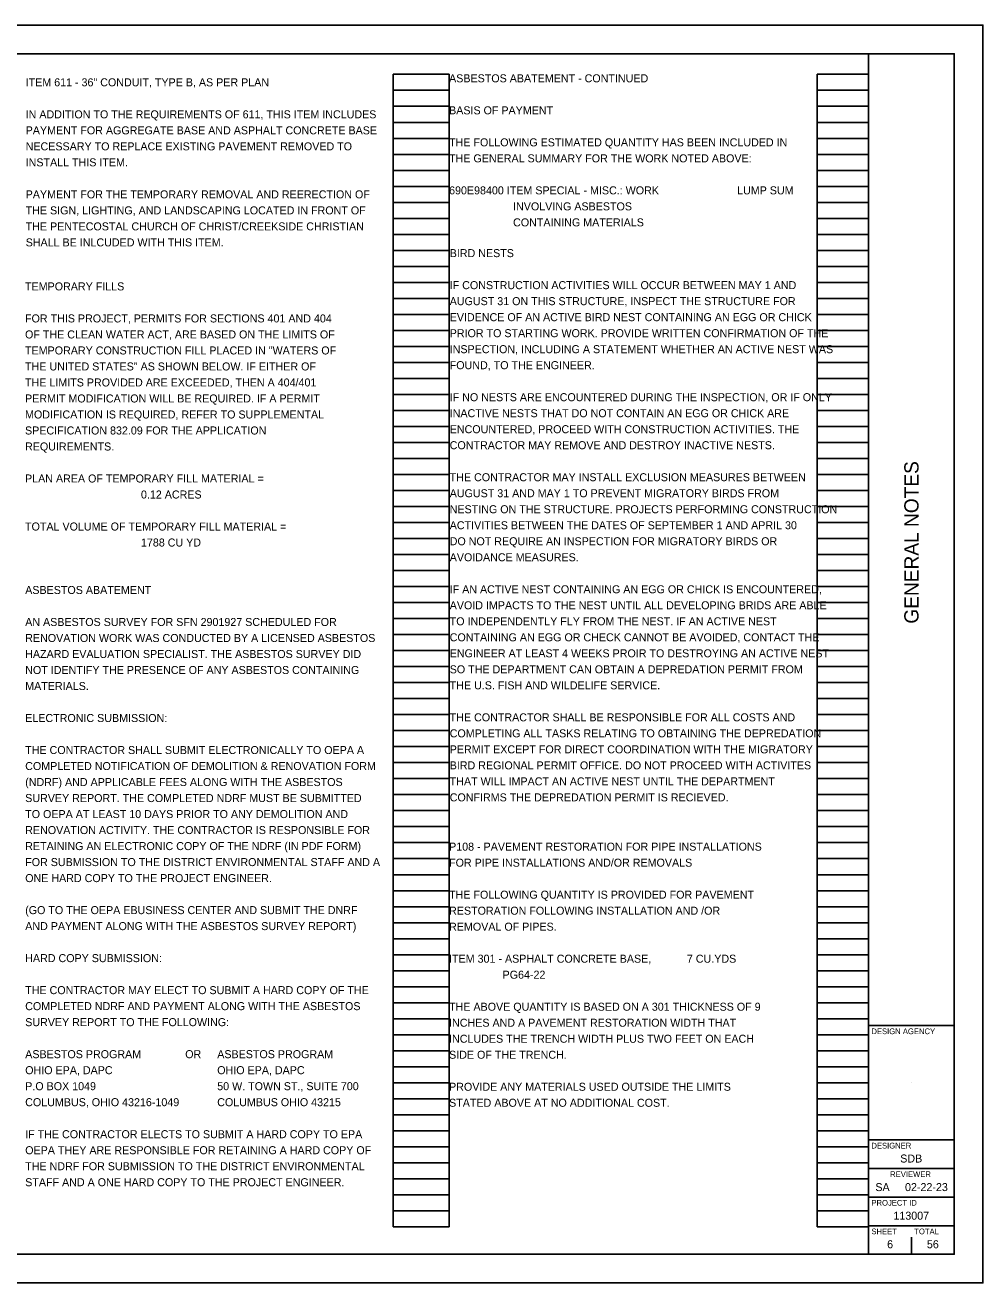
# Model space of a CAD drawing. Extents: x 0 to 34, y 0 to 22.
# Drawn here: x 17.24 to 34, y 0 to 22 of the extents above; entities that cross this region are included whole.
import ezdxf

# ---------------------------------------------------------------- set-up
doc = ezdxf.new("R2010")
doc.units = 0
for name, color, linetype in [('SH_Border', 7, 'Continuous'), ('SH_Cut_Line', 7, 'Continuous'), ('SH_Data', 7, 'Continuous'), ('SH_Text', 7, 'Continuous')]:
    doc.layers.add(name, color=color, linetype=linetype)

msp = doc.modelspace()

# ---------------------------------------------------------------- linework, layer by layer
at = {"layer": 'SH_Border'}
for p, q in [((32, 0.5), (32, 21.5)), ((32, 4.5), (33.5, 4.5)), ((32, 2.5), (33.5, 2.5)), ((32, 2), (33.5, 2)), ((32, 1.5), (33.5, 1.5)), ((32, 1), (33.5, 1))]:
    msp.add_line(p, q, dxfattribs=at)
msp.add_lwpolyline([(1.5, 21.5), (33.5, 21.5), (33.5, 0.5), (1.5, 0.5)], close=True, dxfattribs=at)
at = {"layer": 'SH_Cut_Line'}
msp.add_lwpolyline([(0, 0), (34, 0), (34, 22), (0, 22)], close=True, dxfattribs=at)
at = {"layer": 'SH_Data'}
for p, q in [((23.68, 0.98), (23.68, 21.14)), ((23.68, 21.14), (24.66, 21.14)), ((24.66, 0.98), (24.66, 21.14)), ((31.1, 0.98), (31.1, 21.14)), ((31.1, 21.14), (32, 21.14)), ((32, 0.98), (32, 21.14)), ((23.68, 20.86), (24.66, 20.86)), ((31.1, 20.86), (32, 20.86)), ((23.68, 20.58), (24.66, 20.58)), ((31.1, 20.58), (32, 20.58)), ((23.68, 20.3), (24.66, 20.3)), ((31.1, 20.3), (32, 20.3)), ((23.68, 20.02), (24.66, 20.02)), ((31.1, 20.02), (32, 20.02)), ((23.68, 19.74), (24.66, 19.74)), ((31.1, 19.74), (32, 19.74)), ((23.68, 19.46), (24.66, 19.46)), ((31.1, 19.46), (32, 19.46)), ((23.68, 19.18), (24.66, 19.18)), ((31.1, 19.18), (32, 19.18)), ((23.68, 18.9), (24.66, 18.9)), ((31.1, 18.9), (32, 18.9)), ((23.68, 18.62), (24.66, 18.62)), ((31.1, 18.62), (32, 18.62)), ((23.68, 18.34), (24.66, 18.34)), ((31.1, 18.34), (32, 18.34)), ((23.68, 18.06), (24.66, 18.06)), ((31.1, 18.06), (32, 18.06)), ((23.68, 17.78), (24.66, 17.78)), ((31.1, 17.78), (32, 17.78)), ((23.68, 17.5), (24.66, 17.5)), ((31.1, 17.5), (32, 17.5)), ((23.68, 17.22), (24.66, 17.22)), ((31.1, 17.22), (32, 17.22)), ((23.68, 16.94), (24.66, 16.94)), ((31.1, 16.94), (32, 16.94)), ((23.68, 16.66), (24.66, 16.66)), ((31.1, 16.66), (32, 16.66)), ((23.68, 16.38), (24.66, 16.38)), ((31.1, 16.38), (32, 16.38)), ((23.68, 16.1), (24.66, 16.1)), ((31.1, 16.1), (32, 16.1)), ((23.68, 15.82), (24.66, 15.82)), ((31.1, 15.82), (32, 15.82)), ((23.68, 15.54), (24.66, 15.54)), ((31.1, 15.54), (32, 15.54)), ((23.68, 15.26), (24.66, 15.26)), ((31.1, 15.26), (32, 15.26)), ((23.68, 14.98), (24.66, 14.98)), ((31.1, 14.98), (32, 14.98)), ((23.68, 14.7), (24.66, 14.7)), ((31.1, 14.7), (32, 14.7)), ((23.68, 14.42), (24.66, 14.42)), ((31.1, 14.42), (32, 14.42)), ((23.68, 14.14), (24.66, 14.14)), ((31.1, 14.14), (32, 14.14)), ((23.68, 13.86), (24.66, 13.86)), ((31.1, 13.86), (32, 13.86)), ((23.68, 13.58), (24.66, 13.58)), ((31.1, 13.58), (32, 13.58)), ((23.68, 13.3), (24.66, 13.3)), ((31.1, 13.3), (32, 13.3)), ((23.68, 13.02), (24.66, 13.02)), ((31.1, 13.02), (32, 13.02)), ((23.68, 12.74), (24.66, 12.74)), ((31.1, 12.74), (32, 12.74)), ((23.68, 12.46), (24.66, 12.46)), ((31.1, 12.46), (32, 12.46)), ((23.68, 12.18), (24.66, 12.18)), ((31.1, 12.18), (32, 12.18)), ((23.68, 11.9), (24.66, 11.9)), ((31.1, 11.9), (32, 11.9)), ((23.68, 11.62), (24.66, 11.62)), ((31.1, 11.62), (32, 11.62)), ((23.68, 11.34), (24.66, 11.34)), ((31.1, 11.34), (32, 11.34)), ((23.68, 11.06), (24.66, 11.06)), ((31.1, 11.06), (32, 11.06)), ((23.68, 10.78), (24.66, 10.78)), ((31.1, 10.78), (32, 10.78)), ((23.68, 10.5), (24.66, 10.5)), ((31.1, 10.5), (32, 10.5)), ((23.68, 10.22), (24.66, 10.22)), ((31.1, 10.22), (32, 10.22)), ((23.68, 9.94), (24.66, 9.94)), ((31.1, 9.94), (32, 9.94)), ((23.68, 9.66), (24.66, 9.66)), ((31.1, 9.66), (32, 9.66)), ((23.68, 9.38), (24.66, 9.38)), ((31.1, 9.38), (32, 9.38)), ((23.68, 9.1), (24.66, 9.1)), ((31.1, 9.1), (32, 9.1)), ((23.68, 8.82), (24.66, 8.82)), ((31.1, 8.82), (32, 8.82)), ((23.68, 8.54), (24.66, 8.54)), ((31.1, 8.54), (32, 8.54)), ((23.68, 8.26), (24.66, 8.26)), ((31.1, 8.26), (32, 8.26)), ((23.68, 7.98), (24.66, 7.98)), ((31.1, 7.98), (32, 7.98)), ((23.68, 7.7), (24.66, 7.7)), ((31.1, 7.7), (32, 7.7)), ((23.68, 7.42), (24.66, 7.42)), ((31.1, 7.42), (32, 7.42)), ((23.68, 7.14), (24.66, 7.14)), ((31.1, 7.14), (32, 7.14)), ((23.68, 6.86), (24.66, 6.86)), ((31.1, 6.86), (32, 6.86)), ((23.68, 6.58), (24.66, 6.58)), ((31.1, 6.58), (32, 6.58)), ((23.68, 6.3), (24.66, 6.3)), ((31.1, 6.3), (32, 6.3)), ((23.68, 6.02), (24.66, 6.02)), ((31.1, 6.02), (32, 6.02)), ((23.68, 5.74), (24.66, 5.74)), ((31.1, 5.74), (32, 5.74)), ((23.68, 5.46), (24.66, 5.46)), ((31.1, 5.46), (32, 5.46)), ((23.68, 5.18), (24.66, 5.18)), ((31.1, 5.18), (32, 5.18)), ((23.68, 4.9), (24.66, 4.9)), ((31.1, 4.9), (32, 4.9)), ((23.68, 4.62), (24.66, 4.62)), ((31.1, 4.62), (32, 4.62)), ((23.68, 4.34), (24.66, 4.34)), ((31.1, 4.34), (32, 4.34)), ((23.68, 4.06), (24.66, 4.06)), ((31.1, 4.06), (32, 4.06)), ((23.68, 3.78), (24.66, 3.78)), ((31.1, 3.78), (32, 3.78)), ((23.68, 3.5), (24.66, 3.5)), ((31.1, 3.5), (32, 3.5)), ((32.75, 3.5), (32.75, 3.5)), ((23.68, 3.22), (24.66, 3.22)), ((31.1, 3.22), (32, 3.22)), ((23.68, 2.94), (24.66, 2.94)), ((31.1, 2.94), (32, 2.94)), ((23.68, 2.66), (24.66, 2.66)), ((31.1, 2.66), (32, 2.66)), ((23.68, 2.38), (24.66, 2.38)), ((31.1, 2.38), (32, 2.38)), ((23.68, 2.1), (24.66, 2.1)), ((31.1, 2.1), (32, 2.1)), ((23.68, 1.82), (24.66, 1.82)), ((31.1, 1.82), (32, 1.82)), ((23.68, 1.54), (24.66, 1.54)), ((31.1, 1.54), (32, 1.54)), ((23.68, 1.26), (24.66, 1.26)), ((31.1, 1.26), (32, 1.26)), ((23.68, 0.98), (24.66, 0.98)), ((31.1, 0.98), (32, 0.98)), ((32.375, 0.675), (32.375, 0.675)), ((32.75, 0.5), (32.75, 0.8))]:
    msp.add_line(p, q, dxfattribs=at)

# ---------------------------------------------------------------- texts
msp.add_text('GENERAL NOTES', height=0.25, rotation=90, dxfattribs=at).set_placement((32.875, 11.531))
for s, height, p in [('DESIGN AGENCY', 0.1, (32.05, 4.35)), ('DESIGNER', 0.1, (32.05, 2.35)), ('SDB', 0.14, (32.554, 2.105)), ('REVIEWER', 0.1, (32.378, 1.85)), ('SA', 0.14, (32.119, 1.605)), ('02-22-23', 0.14, (32.638, 1.605)), ('PROJECT ID', 0.1, (32.05, 1.35)), ('113007', 0.14, (32.435, 1.105)), ('SHEET', 0.1, (32.05, 0.85)), ('TOTAL', 0.1, (32.8, 0.85)), ('6', 0.14, (32.325, 0.605)), ('56', 0.14, (33.021, 0.605))]:
    msp.add_text(s, height=height, dxfattribs=at).set_placement(p)
at = {"layer": 'SH_Text'}
for s, p in [('ASBESTOS ABATEMENT - CONTINUED', (24.66, 21)), ('ITEM 611 - 36" CONDUIT, TYPE B, AS PER PLAN', (17.251, 20.93)), ('IN ADDITION TO THE REQUIREMENTS OF 611, THIS ITEM INCLUDES', (17.251, 20.37)), ('BASIS OF PAYMENT', (24.66, 20.44)), ('PAYMENT FOR AGGREGATE BASE AND ASPHALT CONCRETE BASE', (17.251, 20.09)), ('THE FOLLOWING ESTIMATED QUANTITY HAS BEEN INCLUDED IN ', (24.66, 19.88)), ('NECESSARY TO REPLACE EXISTING PAVEMENT REMOVED TO', (17.251, 19.81)), ('INSTALL THIS ITEM.', (17.251, 19.53)), ('THE GENERAL SUMMARY FOR THE WORK NOTED ABOVE:', (24.66, 19.6)), ('690E98400 ITEM SPECIAL - MISC.: WORK ', (24.66, 19.04)), ('LUMP SUM', (29.7, 19.04)), ('PAYMENT FOR THE TEMPORARY REMOVAL AND REERECTION OF', (17.251, 18.97)), ('THE SIGN, LIGHTING, AND LANDSCAPING LOCATED IN FRONT OF', (17.251, 18.69)), ('INVOLVING ASBESTOS ', (25.78, 18.76)), ('THE PENTECOSTAL CHURCH OF CHRIST/CREEKSIDE CHRISTIAN ', (17.251, 18.41)), ('CONTAINING MATERIALS', (25.78, 18.48)), ('SHALL BE INLCUDED WITH THIS ITEM.', (17.251, 18.13)), ('BIRD NESTS', (24.671, 17.942)), ('TEMPORARY FILLS', (17.24, 17.36)), ('IF CONSTRUCTION ACTIVITIES WILL OCCUR BETWEEN MAY 1 AND', (24.671, 17.382)), ('AUGUST 31 ON THIS STRUCTURE, INSPECT THE STRUCTURE FOR', (24.671, 17.102)), ('FOR THIS PROJECT, PERMITS FOR SECTIONS 401 AND 404', (17.24, 16.8)), ('EVIDENCE OF AN ACTIVE BIRD NEST CONTAINING AN EGG OR CHICK', (24.671, 16.822)), ('OF THE CLEAN WATER ACT, ARE BASED ON THE LIMITS OF', (17.24, 16.52)), ('PRIOR TO STARTING WORK. PROVIDE WRITTEN CONFIRMATION OF THE', (24.671, 16.542)), ('TEMPORARY CONSTRUCTION FILL PLACED IN "WATERS OF', (17.24, 16.24)), ('INSPECTION, INCLUDING A STATEMENT WHETHER AN ACTIVE NEST WAS', (24.671, 16.262)), ('THE UNITED STATES" AS SHOWN BELOW. IF EITHER OF', (17.24, 15.96)), ('FOUND, TO THE ENGINEER.', (24.671, 15.982)), ('THE LIMITS PROVIDED ARE EXCEEDED, THEN A 404/401', (17.24, 15.68)), ('PERMIT MODIFICATION WILL BE REQUIRED. IF A PERMIT', (17.24, 15.4)), ('IF NO NESTS ARE ENCOUNTERED DURING THE INSPECTION, OR IF ONLY', (24.671, 15.422)), ('MODIFICATION IS REQUIRED, REFER TO SUPPLEMENTAL', (17.24, 15.12)), ('INACTIVE NESTS THAT DO NOT CONTAIN AN EGG OR CHICK ARE', (24.671, 15.142)), ('SPECIFICATION 832.09 FOR THE APPLICATION', (17.24, 14.84)), ('ENCOUNTERED, PROCEED WITH CONSTRUCTION ACTIVITIES. THE', (24.671, 14.862)), ('REQUIREMENTS.', (17.24, 14.56)), ('CONTRACTOR MAY REMOVE AND DESTROY INACTIVE NESTS.', (24.671, 14.582)), ('PLAN AREA OF TEMPORARY FILL MATERIAL =', (17.24, 14)), ('THE CONTRACTOR MAY INSTALL EXCLUSION MEASURES BETWEEN', (24.671, 14.022)), ('                                       0.12 ACRES', (17.24, 13.72)), ('AUGUST 31 AND MAY 1 TO PREVENT MIGRATORY BIRDS FROM ', (24.671, 13.742)), ('NESTING ON THE STRUCTURE. PROJECTS PERFORMING CONSTRUCTION', (24.671, 13.462)), ('TOTAL VOLUME OF TEMPORARY FILL MATERIAL =', (17.24, 13.16)), ('ACTIVITIES BETWEEN THE DATES OF SEPTEMBER 1 AND APRIL 30', (24.671, 13.182)), ('                                       1788 CU YD', (17.24, 12.88)), ('DO NOT REQUIRE AN INSPECTION FOR MIGRATORY BIRDS OR', (24.671, 12.902)), ('AVOIDANCE MEASURES.', (24.671, 12.622)), ('ASBESTOS ABATEMENT', (17.243, 12.05)), ('IF AN ACTIVE NEST CONTAINING AN EGG OR CHICK IS ENCOUNTERED,', (24.671, 12.062)), ('AVOID IMPACTS TO THE NEST UNTIL ALL DEVELOPING BRIDS ARE ABLE', (24.671, 11.782)), ('AN ASBESTOS SURVEY FOR SFN 2901927 SCHEDULED FOR ', (17.243, 11.49)), ('TO INDEPENDENTLY FLY FROM THE NEST. IF AN ACTIVE NEST', (24.671, 11.502)), ('RENOVATION WORK WAS CONDUCTED BY A LICENSED ASBESTOS ', (17.243, 11.21)), ('CONTAINING AN EGG OR CHECK CANNOT BE AVOIDED, CONTACT THE', (24.671, 11.222)), ('HAZARD EVALUATION SPECIALIST. THE ASBESTOS SURVEY DID ', (17.243, 10.93)), ('ENGINEER AT LEAST 4 WEEKS PROIR TO DESTROYING AN ACTIVE NEST', (24.671, 10.942)), ('NOT IDENTIFY THE PRESENCE OF ANY ASBESTOS CONTAINING ', (17.243, 10.65)), ('SO THE DEPARTMENT CAN OBTAIN A DEPREDATION PERMIT FROM', (24.671, 10.662)), ('MATERIALS.', (17.243, 10.37)), ('THE U.S. FISH AND WILDELIFE SERVICE.', (24.671, 10.382)), ('ELECTRONIC SUBMISSION: ', (17.243, 9.81)), ('THE CONTRACTOR SHALL BE RESPONSIBLE FOR ALL COSTS AND', (24.671, 9.822)), ('COMPLETING ALL TASKS RELATING TO OBTAINING THE DEPREDATION', (24.671, 9.542)), ('THE CONTRACTOR SHALL SUBMIT ELECTRONICALLY TO OEPA A ', (17.243, 9.25)), ('PERMIT EXCEPT FOR DIRECT COORDINATION WITH THE MIGRATORY ', (24.671, 9.262)), ('COMPLETED NOTIFICATION OF DEMOLITION & RENOVATION FORM ', (17.243, 8.97)), ('BIRD REGIONAL PERMIT OFFICE. DO NOT PROCEED WITH ACTIVITES ', (24.671, 8.982)), ('(NDRF) AND APPLICABLE FEES ALONG WITH THE ASBESTOS ', (17.243, 8.69)), ('THAT WILL IMPACT AN ACTIVE NEST UNTIL THE DEPARTMENT', (24.671, 8.702)), ('SURVEY REPORT. THE COMPLETED NDRF MUST BE SUBMITTED ', (17.243, 8.41)), ('CONFIRMS THE DEPREDATION PERMIT IS RECIEVED.', (24.671, 8.422)), ('TO OEPA AT LEAST 10 DAYS PRIOR TO ANY DEMOLITION AND ', (17.243, 8.13)), ('RENOVATION ACTIVITY. THE CONTRACTOR IS RESPONSIBLE FOR ', (17.243, 7.85)), ('RETAINING AN ELECTRONIC COPY OF THE NDRF (IN PDF FORM) ', (17.243, 7.57)), ('P108 - PAVEMENT RESTORATION FOR PIPE INSTALLATIONS ', (24.66, 7.56)), ('FOR SUBMISSION TO THE DISTRICT ENVIRONMENTAL STAFF AND A ', (17.243, 7.29)), ('FOR PIPE INSTALLATIONS AND/OR REMOVALS', (24.66, 7.28)), ('ONE HARD COPY TO THE PROJECT ENGINEER.', (17.243, 7.01)), ('THE FOLLOWING QUANTITY IS PROVIDED FOR PAVEMENT ', (24.66, 6.72)), ('(GO TO THE OEPA EBUSINESS CENTER AND SUBMIT THE DNRF ', (17.243, 6.45)), ('RESTORATION FOLLOWING INSTALLATION AND /OR ', (24.66, 6.44)), ('AND PAYMENT ALONG WITH THE ASBESTOS SURVEY REPORT)', (17.243, 6.17)), ('REMOVAL OF PIPES.', (24.66, 6.16)), ('HARD COPY SUBMISSION:', (17.243, 5.61)), ('ITEM 301 - ASPHALT CONCRETE BASE,            7 CU.YDS', (24.66, 5.6)), ('                  PG64-22  ', (24.66, 5.32)), ('THE CONTRACTOR MAY ELECT TO SUBMIT A HARD COPY OF THE ', (17.243, 5.05)), ('COMPLETED NDRF AND PAYMENT ALONG WITH THE ASBESTOS ', (17.243, 4.77)), ('THE ABOVE QUANTITY IS BASED ON A 301 THICKNESS OF 9 ', (24.66, 4.76)), ('SURVEY REPORT TO THE FOLLOWING:', (17.243, 4.49)), ('INCHES AND A PAVEMENT RESTORATION WIDTH THAT ', (24.66, 4.48)), ('INCLUDES THE TRENCH WIDTH PLUS TWO FEET ON EACH ', (24.66, 4.2)), ('ASBESTOS PROGRAM', (17.243, 3.93)), ('OR', (20.043, 3.93)), ('ASBESTOS PROGRAM', (20.603, 3.93)), ('SIDE OF THE TRENCH.', (24.66, 3.92)), ('OHIO EPA, DAPC', (17.243, 3.65)), ('OHIO EPA, DAPC', (20.603, 3.65)), ('P.O BOX 1049', (17.243, 3.37)), ('50 W. TOWN ST., SUITE 700', (20.603, 3.37)), ('PROVIDE ANY MATERIALS USED OUTSIDE THE LIMITS ', (24.66, 3.36)), ('COLUMBUS, OHIO 43216-1049', (17.243, 3.09)), ('COLUMBUS OHIO 43215', (20.603, 3.09)), ('STATED ABOVE AT NO ADDITIONAL COST.', (24.66, 3.08)), ('IF THE CONTRACTOR ELECTS TO SUBMIT A HARD COPY TO EPA ', (17.243, 2.53)), ('OEPA THEY ARE RESPONSIBLE FOR RETAINING A HARD COPY OF ', (17.243, 2.25)), ('THE NDRF FOR SUBMISSION TO THE DISTRICT ENVIRONMENTAL ', (17.243, 1.97)), ('STAFF AND A ONE HARD COPY TO THE PROJECT ENGINEER.', (17.243, 1.69))]:
    msp.add_text(s, height=0.14, dxfattribs=at).set_placement(p)

doc.saveas('drawing.dxf')
